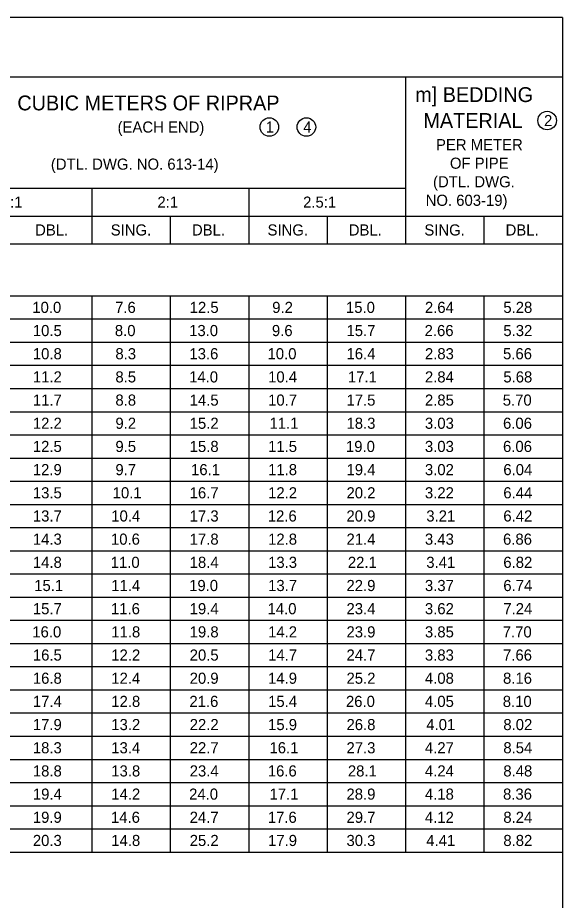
# Model space of a CAD drawing. Extents: x 49991.4 to 50047.6, y 49987.6 to 50011.4.
# Drawn here: x 50044.395 to 50047.334, y 49993.4 to 49998.161 of the extents above; entities that cross this region are included whole.
import ezdxf

# ---------------------------------------------------------------- set-up
doc = ezdxf.new("R2010")
doc.units = 0
doc.layers.add('Level 2', color=7, linetype='Continuous')

msp = doc.modelspace()

# ---------------------------------------------------------------- linework, layer by layer
at = {"layer": 'Level 2'}
for p, q in [((50047.3341, 49998.1607), (50039.4641, 49998.1607)), ((50047.3341, 49998.1607), (50047.3341, 49990.3807)), ((50039.4641, 49997.8407), (50047.3341, 49997.8407)), ((50046.4879, 49997.8407), (50046.4879, 49996.9407)), ((50041.4107, 49997.2407), (50046.4879, 49997.2407)), ((50044.7955, 49997.2407), (50044.7955, 49996.9407)), ((50045.6417, 49997.2407), (50045.6417, 49996.9407)), ((50040.5645, 49997.0907), (50047.3341, 49997.0907)), ((50045.2186, 49997.0907), (50045.2186, 49996.9407)), ((50046.0648, 49997.0907), (50046.0648, 49996.9407)), ((50046.911, 49997.0907), (50046.911, 49996.9407)), ((50039.4641, 49996.9407), (50047.3341, 49996.9407)), ((50039.4641, 49996.6607), (50047.3341, 49996.6607)), ((50044.7955, 49996.6607), (50044.7955, 49993.6607)), ((50045.2186, 49996.6607), (50045.2186, 49993.6607)), ((50045.6417, 49996.6607), (50045.6417, 49993.6607)), ((50046.0648, 49996.6607), (50046.0648, 49993.6607)), ((50046.4879, 49996.6607), (50046.4879, 49993.6607)), ((50046.911, 49996.6607), (50046.911, 49993.6607)), ((50039.4641, 49996.5357), (50047.3341, 49996.5357)), ((50039.4641, 49996.4107), (50047.3341, 49996.4107)), ((50039.4641, 49996.2857), (50047.3341, 49996.2857)), ((50039.4641, 49996.1607), (50047.3341, 49996.1607)), ((50039.4641, 49996.0357), (50047.3341, 49996.0357)), ((50039.4641, 49995.9107), (50047.3341, 49995.9107)), ((50039.4641, 49995.7857), (50047.3341, 49995.7857)), ((50039.4641, 49995.6607), (50047.3341, 49995.6607)), ((50039.4641, 49995.5357), (50047.3341, 49995.5357)), ((50039.4641, 49995.4107), (50047.3341, 49995.4107)), ((50039.4641, 49995.2857), (50047.3341, 49995.2857)), ((50039.4641, 49995.1607), (50047.3341, 49995.1607)), ((50039.4641, 49995.0357), (50047.3341, 49995.0357)), ((50039.4641, 49994.9107), (50047.3341, 49994.9107)), ((50039.4641, 49994.7857), (50047.3341, 49994.7857)), ((50039.4641, 49994.6607), (50047.3341, 49994.6607)), ((50039.4641, 49994.5357), (50047.3341, 49994.5357)), ((50039.4641, 49994.4107), (50047.3341, 49994.4107)), ((50039.4641, 49994.2857), (50047.3341, 49994.2857)), ((50039.4641, 49994.1607), (50047.3341, 49994.1607)), ((50039.4641, 49994.0357), (50047.3341, 49994.0357)), ((50039.4641, 49993.9107), (50047.3341, 49993.9107)), ((50039.4641, 49993.7857), (50047.3341, 49993.7857)), ((50039.4641, 49993.6607), (50047.3341, 49993.6607))]:
    msp.add_line(p, q, dxfattribs=at)
for centre in [(50045.753, 49997.5707), (50045.953, 49997.5707), (50047.252, 49997.6057)]:
    msp.add_circle(centre, 0.05, dxfattribs=at)

# ---------------------------------------------------------------- texts
for s, height, p in [('m] BEDDING', 0.08, (50046.54, 49997.7057)), ('CUBIC METERS OF RIPRAP', 0.08, (50044.3934, 49997.6607)), ('MATERIAL ', 0.08, (50046.5841, 49997.5657)), ('2', 0.06, (50047.235, 49997.5757)), ('(EACH END)', 0.06, (50044.9341, 49997.5407)), ('1', 0.06, (50045.7336, 49997.5407)), ('4', 0.06, (50045.936, 49997.5407)), ('PER METER', 0.06, (50046.6523, 49997.4457)), ('(DTL. DWG. NO. 613-14)', 0.06, (50044.5741, 49997.3407)), ('OF PIPE', 0.06, (50046.7275, 49997.3457)), ('(DTL. DWG.', 0.06, (50046.6362, 49997.2457)), ('1.5:1', 0.06, (50044.2428, 49997.1357)), ('2:1', 0.06, (50045.149, 49997.1357)), ('2.5:1', 0.06, (50045.9352, 49997.1357)), ('NO. 603-19)', 0.06, (50046.5965, 49997.1457)), ('DBL.', 0.06, (50044.4892, 49996.9857)), ('SING.', 0.06, (50044.8971, 49996.9857)), ('DBL.', 0.06, (50045.3354, 49996.9857)), ('SING.', 0.06, (50045.7433, 49996.9857)), ('DBL.', 0.06, (50046.1816, 49996.9857)), ('SING.', 0.06, (50046.5895, 49996.9857)), ('DBL.', 0.06, (50047.0278, 49996.9857)), ('10.0', 0.06, (50044.474, 49996.5682)), (' 7.6', 0.06, (50044.8985, 49996.5682)), ('12.5', 0.06, (50045.3232, 49996.5682)), (' 9.2', 0.06, (50045.7463, 49996.5682)), ('15.0', 0.06, (50046.1664, 49996.5682)), ('2.64', 0.06, (50046.5925, 49996.5682)), ('5.28', 0.06, (50047.0156, 49996.5682)), ('10.5', 0.06, (50044.477, 49996.4432)), (' 8.0', 0.06, (50044.8971, 49996.4432)), ('13.0', 0.06, (50045.3202, 49996.4432)), (' 9.6', 0.06, (50045.7447, 49996.4432)), ('15.7', 0.06, (50046.1694, 49996.4432)), ('2.66', 0.06, (50046.5909, 49996.4432)), ('5.32', 0.06, (50047.0156, 49996.4432)), ('10.8', 0.06, (50044.477, 49996.3182)), (' 8.3', 0.06, (50044.9001, 49996.3182)), ('13.6', 0.06, (50045.3216, 49996.3182)), ('10.0', 0.06, (50045.7433, 49996.3182)), ('16.4', 0.06, (50046.1694, 49996.3182)), ('2.83', 0.06, (50046.5925, 49996.3182)), ('5.66', 0.06, (50047.014, 49996.3182)), ('11.2', 0.06, (50044.477, 49996.1932)), (' 8.5', 0.06, (50044.9001, 49996.1932)), ('14.0', 0.06, (50045.3202, 49996.1932)), ('10.4', 0.06, (50045.7463, 49996.1932)), ('17.1', 0.06, (50046.1768, 49996.1932)), ('2.84', 0.06, (50046.5925, 49996.1932)), ('5.68', 0.06, (50047.0156, 49996.1932)), ('11.7', 0.06, (50044.477, 49996.0682)), (' 8.8', 0.06, (50044.9001, 49996.0682)), ('14.5', 0.06, (50045.3232, 49996.0682)), ('10.7', 0.06, (50045.7463, 49996.0682)), ('17.5', 0.06, (50046.1694, 49996.0682)), ('2.85', 0.06, (50046.5925, 49996.0682)), ('5.70', 0.06, (50047.0126, 49996.0682)), ('12.2', 0.06, (50044.477, 49995.9432)), (' 9.2', 0.06, (50044.9001, 49995.9432)), ('15.2', 0.06, (50045.3232, 49995.9432)), ('11.1', 0.06, (50045.7537, 49995.9432)), ('18.3', 0.06, (50046.1694, 49995.9432)), ('3.03', 0.06, (50046.5925, 49995.9432)), ('6.06', 0.06, (50047.014, 49995.9432)), ('12.5', 0.06, (50044.477, 49995.8182)), (' 9.5', 0.06, (50044.9001, 49995.8182)), ('15.8', 0.06, (50045.3232, 49995.8182)), ('11.5', 0.06, (50045.7463, 49995.8182)), ('19.0', 0.06, (50046.1664, 49995.8182)), ('3.03', 0.06, (50046.5925, 49995.8182)), ('6.06', 0.06, (50047.014, 49995.8182)), ('12.9', 0.06, (50044.4768, 49995.6932)), (' 9.7', 0.06, (50044.9001, 49995.6932)), ('16.1', 0.06, (50045.3306, 49995.6932)), ('11.8', 0.06, (50045.7463, 49995.6932)), ('19.4', 0.06, (50046.1694, 49995.6932)), ('3.02', 0.06, (50046.5925, 49995.6932)), ('6.04', 0.06, (50047.0156, 49995.6932)), ('13.5', 0.06, (50044.477, 49995.5682)), ('10.1', 0.06, (50044.9075, 49995.5682)), ('16.7', 0.06, (50045.3232, 49995.5682)), ('12.2', 0.06, (50045.7463, 49995.5682)), ('20.2', 0.06, (50046.1694, 49995.5682)), ('3.22', 0.06, (50046.5925, 49995.5682)), ('6.44', 0.06, (50047.0156, 49995.5682)), ('13.7', 0.06, (50044.477, 49995.4432)), ('10.4', 0.06, (50044.9001, 49995.4432)), ('17.3', 0.06, (50045.3232, 49995.4432)), ('12.6', 0.06, (50045.7447, 49995.4432)), ('20.9', 0.06, (50046.1692, 49995.4432)), ('3.21', 0.06, (50046.5999, 49995.4432)), ('6.42', 0.06, (50047.0156, 49995.4432)), ('14.3', 0.06, (50044.477, 49995.3182)), ('10.6', 0.06, (50044.8985, 49995.3182)), ('17.8', 0.06, (50045.3232, 49995.3182)), ('12.8', 0.06, (50045.7463, 49995.3182)), ('21.4', 0.06, (50046.1694, 49995.3182)), ('3.43', 0.06, (50046.5925, 49995.3182)), ('6.86', 0.06, (50047.014, 49995.3182)), ('14.8', 0.06, (50044.477, 49995.1932)), ('11.0', 0.06, (50044.8971, 49995.1932)), ('18.4', 0.06, (50045.3232, 49995.1932)), ('13.3', 0.06, (50045.7463, 49995.1932)), ('22.1', 0.06, (50046.1768, 49995.1932)), ('3.41', 0.06, (50046.5999, 49995.1932)), ('6.82', 0.06, (50047.0156, 49995.1932)), ('15.1', 0.06, (50044.4844, 49995.0682)), ('11.4', 0.06, (50044.9001, 49995.0682)), ('19.0', 0.06, (50045.3202, 49995.0682)), ('13.7', 0.06, (50045.7463, 49995.0682)), ('22.9', 0.06, (50046.1692, 49995.0682)), ('3.37', 0.06, (50046.5925, 49995.0682)), ('6.74', 0.06, (50047.0156, 49995.0682)), ('15.7', 0.06, (50044.477, 49994.9432)), ('11.6', 0.06, (50044.8985, 49994.9432)), ('19.4', 0.06, (50045.3232, 49994.9432)), ('14.0', 0.06, (50045.7433, 49994.9432)), ('23.4', 0.06, (50046.1694, 49994.9432)), ('3.62', 0.06, (50046.5925, 49994.9432)), ('7.24', 0.06, (50047.0156, 49994.9432)), ('16.0', 0.06, (50044.474, 49994.8182)), ('11.8', 0.06, (50044.9001, 49994.8182)), ('19.8', 0.06, (50045.3232, 49994.8182)), ('14.2', 0.06, (50045.7463, 49994.8182)), ('23.9', 0.06, (50046.1692, 49994.8182)), ('3.85', 0.06, (50046.5925, 49994.8182)), ('7.70', 0.06, (50047.0126, 49994.8182)), ('16.5', 0.06, (50044.477, 49994.6932)), ('12.2', 0.06, (50044.9001, 49994.6932)), ('20.5', 0.06, (50045.3232, 49994.6932)), ('24.7', 0.06, (50046.1694, 49994.6932)), ('3.83', 0.06, (50046.5925, 49994.6932)), ('7.66', 0.06, (50047.014, 49994.6932)), ('14.7', 0.06, (50045.7463, 49994.6932)), ('16.8', 0.06, (50044.477, 49994.5682)), ('12.4', 0.06, (50044.9001, 49994.5682)), ('20.9', 0.06, (50045.323, 49994.5682)), ('14.9', 0.06, (50045.7461, 49994.5682)), ('25.2', 0.06, (50046.1694, 49994.5682)), ('4.08', 0.06, (50046.5925, 49994.5682)), ('8.16', 0.06, (50047.014, 49994.5682)), ('17.4', 0.06, (50044.477, 49994.4432)), ('12.8', 0.06, (50044.9001, 49994.4432)), ('21.6', 0.06, (50045.3216, 49994.4432)), ('15.4', 0.06, (50045.7463, 49994.4432)), ('26.0', 0.06, (50046.1664, 49994.4432)), ('4.05', 0.06, (50046.5925, 49994.4432)), ('8.10', 0.06, (50047.0126, 49994.4432)), ('17.9', 0.06, (50044.4768, 49994.3182)), ('13.2', 0.06, (50044.9001, 49994.3182)), ('22.2', 0.06, (50045.3232, 49994.3182)), ('15.9', 0.06, (50045.7461, 49994.3182)), ('26.8', 0.06, (50046.1694, 49994.3182)), ('4.01', 0.06, (50046.5999, 49994.3182)), ('8.02', 0.06, (50047.0156, 49994.3182)), ('18.3', 0.06, (50044.477, 49994.1932)), ('13.4', 0.06, (50044.9001, 49994.1932)), ('22.7', 0.06, (50045.3232, 49994.1932)), ('16.1', 0.06, (50045.7537, 49994.1932)), ('27.3', 0.06, (50046.1694, 49994.1932)), ('4.27', 0.06, (50046.5925, 49994.1932)), ('8.54', 0.06, (50047.0156, 49994.1932)), ('18.8', 0.06, (50044.477, 49994.0682)), ('13.8', 0.06, (50044.9001, 49994.0682)), ('23.4', 0.06, (50045.3232, 49994.0682)), ('16.6', 0.06, (50045.7447, 49994.0682)), ('28.1', 0.06, (50046.1768, 49994.0682)), ('4.24', 0.06, (50046.5925, 49994.0682)), ('8.48', 0.06, (50047.0156, 49994.0682)), ('19.4', 0.06, (50044.477, 49993.9432)), ('14.2', 0.06, (50044.9001, 49993.9432)), ('24.0', 0.06, (50045.3202, 49993.9432)), ('17.1', 0.06, (50045.7537, 49993.9432)), ('28.9', 0.06, (50046.1692, 49993.9432)), ('4.18', 0.06, (50046.5925, 49993.9432)), ('8.36', 0.06, (50047.014, 49993.9432)), ('19.9', 0.06, (50044.4768, 49993.8182)), ('14.6', 0.06, (50044.8985, 49993.8182)), ('24.7', 0.06, (50045.3232, 49993.8182)), ('17.6', 0.06, (50045.7447, 49993.8182)), ('29.7', 0.06, (50046.1694, 49993.8182)), ('4.12', 0.06, (50046.5925, 49993.8182)), ('8.24', 0.06, (50047.0156, 49993.8182)), ('20.3', 0.06, (50044.477, 49993.6932)), ('14.8', 0.06, (50044.9001, 49993.6932)), ('25.2', 0.06, (50045.3232, 49993.6932)), ('17.9', 0.06, (50045.7461, 49993.6932)), ('30.3', 0.06, (50046.1694, 49993.6932)), ('4.41', 0.06, (50046.5999, 49993.6932)), ('8.82', 0.06, (50047.0156, 49993.6932))]:
    msp.add_text(s, height=height, dxfattribs=at).set_placement(p)

doc.saveas('drawing.dxf')
